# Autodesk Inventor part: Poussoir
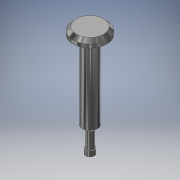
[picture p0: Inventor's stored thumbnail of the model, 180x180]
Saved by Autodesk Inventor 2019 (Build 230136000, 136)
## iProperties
Created: 2018-06
Part Number: Poussoir
Material: Acier inoxydable
Document SubType Name: Modeling
Designer: Fabian Perrée
Density: 8 g/cm^3
Appearance: Semi-poli
Author: Fabian Perrée
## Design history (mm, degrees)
sketch "Esquisse1"
  geometry: L1 (0, 0)-(0, 32.5); L2 (0, 32.5)-(4, 32.5); L3 (5, 31.5)-(5, 30.5); L4 (5, 30.5)-(2.25, 30.5); L5 (1.25, 6.5)-(1, 6.5); L6 (1, 6.5)-(1, 1.5); L7 (1, 1.5)-(1.25, 1.5); L8 (1.25, 1.5)-(1.25, 0); L9 (1.25, 0)-(0, 0); L10 (2.25, 30.5)-(2.25, 7.5); L11 (2.25, 7.5)-(1.25, 6.5); L12 (4, 32.5)-(5, 31.5); 2 further points
  constraints: 24 end point, 5 perpendicular, 4 point on line, 2 vertical, 1 horizontal
  dimensions: "d0" = 32.5 distance of L1.start L1.end; "d1" = 2 distance of point (5, 32.5) L3.end; "d3" = 2 diameter of L6 L1; "d4" = 2.5 diameter of L8 L1; "d5" = 4.5 diameter of L10 L1; "d6" = 24 distance from line of L4 L5.end; "d7" = 1.5 distance of L7.end L8.end; "d8" = 10 diameter of L3 L1; "d9" = 1 distance of L10.end point (2.25, 6.5); "d10" = 1 distance of L5.start point (2.25, 6.5) (= d9); "d11" = 1 distance of L2.end point (5, 32.5) (= d9); "d12" = 1 distance of L3.start point (5, 32.5) (= d11)
revolve "Révolution1" sketch "Esquisse1" stored, may be unused: angle "d13" = 90 deg
node "Solide1"
